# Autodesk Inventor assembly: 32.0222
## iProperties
Created: 2011-07
Part Number: 32.0222
Document SubType Name: Assembly
Designer: Administrator
Description: RAIL HOLDER
Stock Number: 32.0222 RAIL HOLDER
Author: Administrator
